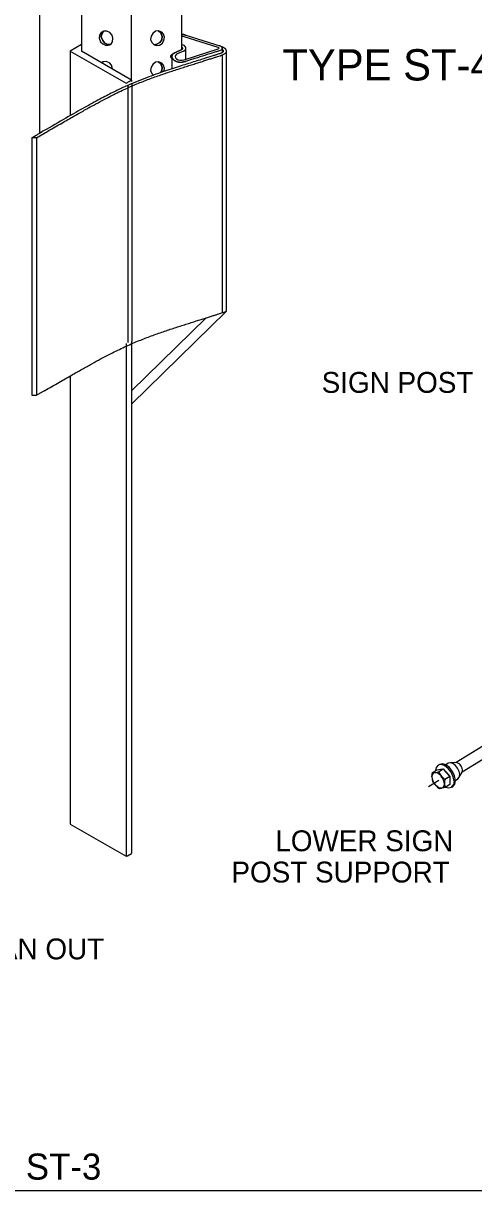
# Model space of a CAD drawing. Extents: x 99862 to 103680, y 99470 to 102076.
# Drawn here: x 101638 to 101984, y 100000 to 100895 of the extents above; entities that cross this region are included whole.
import ezdxf

# ---------------------------------------------------------------- set-up
doc = ezdxf.new("R2010")
doc.units = 0
for name, color, linetype in [('Level 1', 7, 'Continuous'), ('Level 15', 7, 'Continuous'), ('Level 2', 7, 'Continuous'), ('Level 20', 7, 'Continuous'), ('Level 27', 7, 'Continuous'), ('Level 3', 7, 'Continuous'), ('Level 4', 7, 'Continuous'), ('Level 5', 7, 'Continuous'), ('Level 6', 7, 'Continuous'), ('Level 8', 7, 'Continuous'), ('Level 9', 7, 'Continuous')]:
    doc.layers.add(name, color=color, linetype=linetype)

msp = doc.modelspace()

# ---------------------------------------------------------------- linework, layer by layer
at = {"layer": 'Level 1'}
msp.add_lwpolyline([(99862, 99999.5), (103151, 99999.5), (103151, 102075.5), (99862, 102075.5)], close=True, dxfattribs=at)
at = {"layer": 'Level 15'}
msp.add_line((101948.77, 100309.47), (101956.86, 100314.4), dxfattribs=at)
at = {"layer": 'Level 2'}
for p, q in [((101759.42, 100875.03), (101759.42, 101050.75)), ((101720.9, 100850.43), (101720.9, 101028.51)), ((101682.38, 100920.34), (101682.38, 100873.79)), ((101696.25, 100885.97), (101695.9, 100883.63)), ((101695.9, 100883.63), (101696.93, 100880.95)), ((101697.62, 100887.98), (101696.25, 100885.97)), ((101699.33, 100888.99), (101697.62, 100887.98)), ((101697.96, 100886.98), (101697.62, 100884.63)), ((101697.62, 100884.63), (101697.96, 100886.98)), ((101697.62, 100884.63), (101698.65, 100881.95)), ((101698.65, 100881.95), (101697.62, 100884.63)), ((101699.33, 100888.99), (101697.96, 100886.98)), ((101697.96, 100886.98), (101699.33, 100888.99)), ((101701.74, 100888.99), (101699.33, 100888.99)), ((101704.14, 100887.98), (101701.74, 100888.99)), ((101705.85, 100885.97), (101704.14, 100887.98)), ((101706.54, 100883.63), (101705.85, 100885.97)), ((101706.19, 100880.95), (101706.54, 100883.63)), ((101735.78, 100885.33), (101735.44, 100882.64)), ((101737.16, 100887.34), (101735.78, 100885.33)), ((101739.21, 100889.01), (101737.16, 100887.34)), ((101741.62, 100889.35), (101739.21, 100889.01)), ((101743.33, 100887.67), (101741.62, 100889.35)), ((101744.02, 100888.34), (101741.62, 100889.35)), ((101741.62, 100889.35), (101743.33, 100887.67)), ((101744.36, 100884.99), (101743.33, 100887.67)), ((101743.33, 100887.67), (101744.36, 100884.99)), ((101745.39, 100886.67), (101744.02, 100888.34)), ((101744.02, 100882.31), (101744.36, 100884.99)), ((101744.36, 100884.99), (101744.02, 100882.31)), ((101746.08, 100884.32), (101745.39, 100886.67)), ((101745.73, 100881.97), (101746.08, 100884.32)), ((101696.93, 100880.95), (101698.65, 100879.27)), ((101698.65, 100881.95), (101700.36, 100879.94)), ((101700.36, 100879.94), (101698.65, 100881.95)), ((101698.65, 100879.27), (101700.71, 100878.26)), ((101700.36, 100879.94), (101702.42, 100878.93)), ((101702.42, 100878.93), (101700.36, 100879.94)), ((101700.71, 100878.26), (101702.76, 100878.26)), ((101702.42, 100878.93), (101704.82, 100878.93)), ((101704.82, 100878.93), (101702.42, 100878.93)), ((101702.76, 100878.26), (101704.82, 100878.93)), ((101704.82, 100878.93), (101706.19, 100880.95)), ((101735.44, 100882.64), (101736.47, 100880.3)), ((101736.47, 100880.3), (101738.19, 100878.62)), ((101738.19, 100878.62), (101740.24, 100878.96)), ((101740.24, 100878.96), (101738.19, 100878.62)), ((101738.19, 100878.62), (101740.24, 100877.95)), ((101740.24, 100878.96), (101742.65, 100880.3)), ((101742.65, 100880.3), (101740.24, 100878.96)), ((101740.24, 100877.95), (101742.3, 100878.29)), ((101742.3, 100878.29), (101744.36, 100879.63)), ((101742.65, 100880.3), (101744.02, 100882.31)), ((101744.02, 100882.31), (101742.65, 100880.3)), ((101744.36, 100879.63), (101745.73, 100881.97)), ((101698.99, 100865.53), (101697.85, 100864.86)), ((101698.99, 100865.53), (101698.25, 100864.63)), ((101701.39, 100865.86), (101698.99, 100865.53)), ((101703.79, 100864.86), (101701.39, 100865.86)), ((101741.62, 100865.55), (101739.21, 100865.21)), ((101743.33, 100863.87), (101741.62, 100865.55)), ((101744.02, 100864.54), (101741.62, 100865.55)), ((101741.62, 100865.55), (101743.33, 100863.87)), ((101705.51, 100862.84), (101703.79, 100864.86)), ((101706.19, 100860.16), (101705.51, 100862.84)), ((101735.78, 100861.53), (101735.44, 100858.84)), ((101735.44, 100858.84), (101736.47, 100856.5)), ((101737.16, 100863.54), (101735.78, 100861.53)), ((101739.21, 100865.21), (101737.16, 100863.54)), ((101744.36, 100861.19), (101743.33, 100863.87)), ((101743.33, 100863.87), (101744.36, 100861.19)), ((101743.33, 100857.5), (101744.02, 100858.51)), ((101745.39, 100862.87), (101744.02, 100864.54)), ((101744.02, 100858.51), (101744.36, 100861.19)), ((101744.36, 100861.19), (101744.02, 100858.51)), ((101746.08, 100860.52), (101745.39, 100862.87)), ((101745.73, 100858.17), (101746.08, 100860.52)), ((101736.47, 100856.5), (101737.37, 100855.62))]:
    msp.add_line(p, q, dxfattribs=at)
msp.add_lwpolyline([(101716.62, 100256.06), (101717.76, 100256.34), (101720.9, 100258.08)], dxfattribs=at)
at = {"layer": 'Level 27'}
for p, q in [((101790.58, 100673.05), (101790.58, 100870.72)), ((101718.16, 100650.22), (101718.16, 100847.89)), ((101721.4, 100650.95), (101721.4, 100848.62))]:
    msp.add_line(p, q, dxfattribs=at)
at = {"layer": 'Level 3'}
for p, q in [((101682.38, 100878.73), (101673.82, 100873.79)), ((101673.82, 100873.79), (101673.82, 100824.37)), ((101673.82, 100873.79), (101716.62, 100849.08)), ((101720.9, 100851.55), (101682.38, 100873.79)), ((101716.62, 100849.08), (101720.9, 100851.55)), ((101720.9, 100851.55), (101720.9, 100850.43)), ((101720.9, 100651.08), (101720.9, 100258.08)), ((101716.62, 100649.33), (101716.62, 100256.06)), ((101673.82, 100624.62), (101673.82, 100558.98)), ((101673.82, 100558.98), (101673.82, 100280.77)), ((101954.73, 100324.15), (101954.34, 100321.73)), ((101966.57, 100308.96), (101968.04, 100310.75)), ((101968.49, 100313.56), (101968.04, 100310.75)), ((101673.82, 100280.77), (101716.62, 100256.06))]:
    msp.add_line(p, q, dxfattribs=at)
for points in [[(101956.2, 100325.95), (101954.73, 100324.15), (101954.73, 100324.15)], [(101958.45, 100326.44), (101956.2, 100325.95), (101956.2, 100325.95)], [(101961.16, 100325.57), (101958.45, 100326.44), (101958.45, 100326.44)], [(101963.89, 100323.47), (101961.16, 100325.57), (101961.16, 100325.57)], [(101966.25, 100320.44), (101963.89, 100323.47), (101963.89, 100323.47)], [(101967.86, 100316.97), (101966.25, 100320.44), (101966.25, 100320.44)], [(101968.49, 100313.56), (101968.49, 100313.56), (101967.86, 100316.97), (101967.86, 100316.97)], [(101962.22, 100309.13), (101964.31, 100308.46), (101964.31, 100308.46)], [(101964.31, 100308.46), (101966.57, 100308.96), (101966.57, 100308.96)]]:
    msp.add_lwpolyline(points, dxfattribs=at)
at = {"layer": 'Level 4'}
for p, q in [((101650.47, 100810.89), (101650.47, 100936.69)), ((101793.73, 100674.18), (101793.73, 100873.79)), ((101647.49, 100809.17), (101652.27, 100811.93)), ((101644.33, 100807.34), (101647.49, 100809.17)), ((101644.33, 100807.34), (101644.33, 100609.67)), ((101647.92, 100807.34), (101644.33, 100807.34)), ((101647.92, 100807.34), (101654.78, 100811.3)), ((101647.92, 100807.34), (101647.92, 100609.67)), ((101647.92, 100609.67), (101654.57, 100613.51))]:
    msp.add_line(p, q, dxfattribs=at)
for points, degree in [([(101790.59, 100874.92), (101791.19, 100874.41), (101791.19, 100873.79), (101791.19, 100872.59), (101789.36, 100872.01), (101752.99, 100860.55), (101716.62, 100849.08), (101683.55, 100829.98), (101650.47, 100810.89)], 4), ([(101793.73, 100873.83), (101793.69, 100875.88), (101790.58, 100876.86), (101790.31, 100876.94), (101790.03, 100877.03)], 4), ([(101654.07, 100810.89), (101686.11, 100829.39), (101718.16, 100847.89), (101754.37, 100859.31), (101790.58, 100870.72), (101793.48, 100871.64), (101793.72, 100873.54)], 4), ([(101654.07, 100613.22), (101686.11, 100631.72), (101718.16, 100650.22), (101754.37, 100661.63), (101790.58, 100673.05), (101792.27, 100673.58), (101793.73, 100674.18)], 4), ([(101644.33, 100609.67), (101646.12, 100609.67), (101647.92, 100609.67)], 2)]:
    msp.add_open_spline(points, degree=degree, dxfattribs=at)
at = {"layer": 'Level 5'}
for p, q in [((102001.88, 100347.49), (101970.17, 100327.99)), ((101956.2, 100325.95), (101957.23, 100326.49))]:
    msp.add_line(p, q, dxfattribs=at)
for points in [[(102006.46, 100340.05), (101974.75, 100320.54)], [(101966.72, 100309.14), (101967.58, 100309.66), (101969.04, 100311.45), (101969.49, 100314.24), (101968.87, 100317.62), (101967.26, 100321.06), (101964.91, 100324.06), (101962.18, 100326.14), (101959.48, 100326.99), (101957.23, 100326.49)], [(101969.47, 100314.1), (101971.45, 100315.32), (101972.51, 100316.6), (101972.83, 100318.61), (101972.8, 100319.1), (101972.38, 100321.03), (101971.23, 100323.51), (101969.54, 100325.65), (101967.58, 100327.15), (101965.64, 100327.76), (101964.03, 100327.4), (101962.04, 100326.18)], [(101972.51, 100316.6), (101972.51, 100316.6), (101974.76, 100320.55), (101974.98, 100321.89), (101974.96, 100322.22), (101974.68, 100323.51), (101973.91, 100325.16), (101972.78, 100326.59), (101971.48, 100327.58), (101970.19, 100327.99), (101970.19, 100327.99), (101965.64, 100327.76)]]:
    msp.add_lwpolyline(points, dxfattribs=at)
at = {"layer": 'Level 6'}
for p, q in [((101720.9, 100602.89), (101793.73, 100674.18)), ((101778.21, 100669.15), (101720.9, 100613.05))]:
    msp.add_line(p, q, dxfattribs=at)
at = {"layer": 'Level 8'}
for p, q in [((101787.44, 100876.5), (101761.23, 100884.76)), ((101762.45, 100886.05), (101788.66, 100877.79)), ((101759.42, 100878.75), (101760.62, 100878.21)), ((101761.19, 100867.12), (101787.44, 100875.4)), ((101762.52, 100867.54), (101762.52, 100875.95)), ((101790.55, 100872.63), (101790.55, 100875.95)), ((101751.66, 100869.51), (101751.66, 100860.13)), ((101760.62, 100873.69), (101755.36, 100871.32)), ((101788.66, 100871.95), (101788.66, 100871.79)), ((101762.41, 100863.67), (101762.41, 100863.51))]:
    msp.add_line(p, q, dxfattribs=at)
for centre, major_axis, start_param, end_param in [((101758.97, 100882.37), (7.26, 0), 1.071036, 1.509173), ((101758.97, 100882.37), (-4.72, 0), 4.212629, 4.617501), ((101757.56, 100875.95), (-4.96, 0), 2.234021, 4.049164), ((101786.92, 100875.95), (-1.09, 0), 2.070557, 4.212629), ((101786.92, 100875.95), (3.63, 0), 0.571369, 1.071036), ((101786.92, 100875.95), (3.63, 0), 5.212149, 6.815355), ((101758.93, 100869.51), (7.26, 0), 2.355531, 5.212149), ((101758.93, 100869.51), (-4.72, 0), 5.562042, 8.353742)]:
    msp.add_ellipse(centre, major_axis=major_axis, ratio=0.57735, start_param=start_param, end_param=end_param, dxfattribs=at)
for points, degree in [([(101759.42, 100886.56), (101761.03, 100886.5), (101762.45, 100886.05)], 2), ([(101790.05, 100877.01), (101790.55, 100876.52), (101790.55, 100875.95), (101790.55, 100874.7), (101788.66, 100874.11), (101775.53, 100869.97), (101762.41, 100865.83), (101756.88, 100864.09), (101753.11, 100867), (101749.34, 100869.91), (101753.79, 100872.48), (101756.42, 100873.66), (101759.05, 100874.85), (101761.02, 100875.74), (101759.42, 100876.85)], 4), ([(101788.66, 100877.79), (101789.53, 100877.51), (101790.04, 100877.02)], 2)]:
    msp.add_open_spline(points, degree=degree, dxfattribs=at)
at = {"layer": 'Level 9'}
msp.add_line((101956.51, 100320.73), (101960.22, 100323.01), dxfattribs=at)
msp.add_line((101956.51, 100320.73), (101960.22, 100323.01), dxfattribs=at)
for points in [[(101951.49, 100316.94), (101951.48, 100317), (101951.63, 100318.95), (101951.65, 100319.2), (101951.81, 100320.18), (101955.52, 100322.46), (101958.16, 100322.77)], [(101951.49, 100316.94), (101951.48, 100317), (101951.63, 100318.95), (101951.65, 100319.2), (101951.81, 100320.18), (101955.52, 100322.46), (101958.16, 100322.77)], [(101953.65, 100320.19), (101952.49, 100319.67), (101951.74, 100318.53), (101951.49, 100316.94)], [(101953.65, 100320.19), (101952.49, 100319.67), (101951.74, 100318.53), (101951.49, 100316.94)], [(101953.85, 100320.22), (101953.65, 100320.19), (101953.38, 100320.17), (101952.43, 100320.15), (101952.2, 100320.15), (101951.81, 100320.18)], [(101953.85, 100320.22), (101953.65, 100320.19), (101953.38, 100320.17), (101952.43, 100320.15), (101952.2, 100320.15), (101951.81, 100320.18)], [(101957.72, 100318.67), (101958.48, 100317.68), (101956.96, 100319.1), (101955.34, 100319.99), (101953.85, 100320.22), (101954.38, 100320.29), (101955.55, 100320.53), (101956.51, 100320.73), (101957.19, 100319.58), (101957.72, 100318.67)], [(101957.72, 100318.67), (101958.48, 100317.68), (101956.96, 100319.1), (101955.34, 100319.99), (101953.85, 100320.22), (101954.38, 100320.29), (101955.55, 100320.53), (101956.51, 100320.73), (101957.19, 100319.58), (101957.72, 100318.67)], [(101958.16, 100322.77), (101960.22, 100323.01), (101962.02, 100320.9)], [(101958.4, 100322.8), (101960.22, 100323.01), (101962.02, 100320.9)], [(101962.02, 100320.9), (101965.1, 100317.29), (101965.18, 100314.16)], [(101962.11, 100320.8), (101965.1, 100317.29), (101965.18, 100314.39)], [(101951.49, 100316.94), (101951.49, 100316.64), (101951.58, 100315.71), (101951.77, 100314.85), (101951.99, 100313.9)], [(101951.49, 100316.94), (101951.49, 100316.64), (101951.58, 100315.71), (101951.77, 100314.85), (101951.99, 100313.9)], [(101951.49, 100316.64), (101951.84, 100314.72), (101952.7, 100312.7), (101953.93, 100310.89)], [(101951.49, 100316.64), (101951.84, 100314.72), (101952.7, 100312.7), (101953.93, 100310.89)], [(101954.1, 100310.68), (101953.93, 100310.89), (101953.85, 100310.98), (101952.65, 100312.74), (101952.47, 100313), (101951.99, 100313.9)], [(101954.1, 100310.68), (101953.93, 100310.89), (101953.85, 100310.98), (101952.65, 100312.74), (101952.47, 100313), (101951.99, 100313.9)], [(101954.1, 100310.68), (101954.94, 100309.8), (101955.86, 100309.02), (101956.87, 100308.17), (101957.25, 100308.14), (101957.52, 100308.12), (101957.54, 100308.12), (101958.8, 100308.19)], [(101958.8, 100308.19), (101957.3, 100308.38), (101955.65, 100309.25), (101954.1, 100310.68)], [(101954.1, 100310.68), (101954.94, 100309.8), (101955.86, 100309.02), (101956.87, 100308.17), (101957.25, 100308.14), (101957.52, 100308.12), (101957.54, 100308.12), (101958.8, 100308.19)], [(101958.8, 100308.19), (101957.3, 100308.38), (101955.65, 100309.25), (101954.1, 100310.68)], [(101965.1, 100317.29), (101961.39, 100315.01), (101960.53, 100315.67), (101960.3, 100315.9), (101958.71, 100317.42), (101958.59, 100317.55), (101958.48, 100317.68)], [(101965.1, 100317.29), (101961.39, 100315.01), (101960.53, 100315.67), (101960.3, 100315.9), (101958.71, 100317.42), (101958.59, 100317.55), (101958.48, 100317.68)], [(101958.8, 100308.19), (101960.01, 100308.69), (101960.81, 100309.87), (101961.06, 100311.57), (101960.73, 100313.6), (101959.85, 100315.7), (101958.59, 100317.55)], [(101958.8, 100308.19), (101960.01, 100308.69), (101960.81, 100309.87), (101961.06, 100311.57), (101960.73, 100313.6), (101959.85, 100315.7), (101958.59, 100317.55)], [(101965.18, 100314.16), (101965.27, 100311), (101961.57, 100308.72), (101960.49, 100308.5), (101959.43, 100308.28), (101958.8, 100308.19)], [(101965.18, 100314.16), (101965.27, 100311), (101961.57, 100308.72), (101960.49, 100308.5), (101959.43, 100308.28), (101958.8, 100308.19)], [(101961.39, 100315.01), (101961.22, 100313.72), (101961.09, 100312.8), (101961.07, 100311.58), (101961.07, 100311.39), (101961.32, 100309.69), (101961.35, 100309.47), (101961.57, 100308.72)], [(101961.39, 100315.01), (101961.22, 100313.72), (101961.09, 100312.8), (101961.07, 100311.58), (101961.07, 100311.39), (101961.32, 100309.69), (101961.35, 100309.47), (101961.57, 100308.72)]]:
    msp.add_lwpolyline(points, dxfattribs=at)

# ---------------------------------------------------------------- texts
at = {"layer": 'Level 20'}
for s, height, p in [('TYPE ST-4 SIGN SUPPORT', 24, (101836.64, 100851.21)), ('SIGN POST', 16, (101866.81, 100611.58)), ('LOWER SIGN', 16, (101831.23, 100259.91)), ('POST SUPPORT', 16, (101797.52, 100235.91)), ('TYPE ST-3', 20, (101562.36, 100007.98))]:
    msp.add_text(s, height=height, dxfattribs=at).set_placement(p)
msp.add_text('CLEAN OUT', height=16, rotation=360, dxfattribs=at).set_placement((101577.39, 100176.95))

doc.saveas('drawing.dxf')
